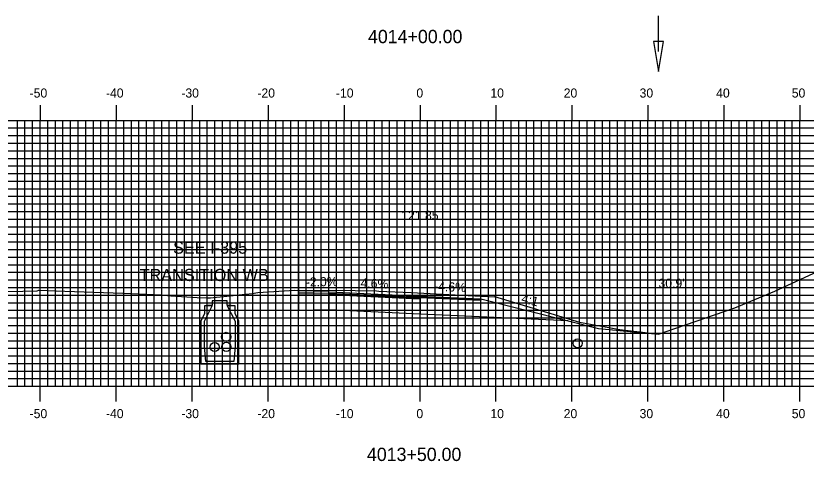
# Model space of a CAD drawing. Extents: x 853328 to 853671, y 364661 to 364881.
# Drawn here: x 853440.1 to 853544.1, y 364731.5 to 364790.1 of the extents above; entities that cross this region are included whole.
import ezdxf

# ---------------------------------------------------------------- set-up
doc = ezdxf.new("R2010")
doc.units = 0
for name, color, linetype in [('ANNOTATION', 7, 'Continuous'), ('D_Drainage_Ditch_Line', 7, 'Continuous'), ('D_Roadway_Centerline_Text', 7, 'Continuous'), ('D_Roadway_Edge_Shoulder', 7, 'Continuous'), ('D_Roadway_Edge_TW', 7, 'Continuous'), ('D_Roadway_Pavement', 7, 'Continuous'), ('D_Roadway_SubGrade', 7, 'Continuous'), ('D_Text_Standard', 7, 'Continuous'), ('H_V ANNOTATION', 7, 'Continuous'), ('M_Roadway_Centerline', 7, 'Continuous'), ('MAJOR', 7, 'Continuous'), ('MINOR', 7, 'Continuous'), ('S_Drainage_CB', 7, 'Continuous'), ('S_Drainage_Invert', 7, 'Continuous'), ('S_Roadway_Centerline', 7, 'Continuous')]:
    doc.layers.add(name, color=color, linetype=linetype)

msp = doc.modelspace()

# ---------------------------------------------------------------- linework, layer by layer
at = {"layer": 'ANNOTATION'}
for p, q in [((853512.79, 364749.99), (853516.79, 364748.99)), ((853516.79, 364748.99), (853524.69, 364748.23))]:
    msp.add_line(p, q, dxfattribs=at)
at = {"layer": 'D_Drainage_Ditch_Line'}
msp.add_line((853524.69, 364785.43), (853524.69, 364790.13), dxfattribs=at)
msp.add_lwpolyline([(853525.34, 364786.75), (853524.03, 364786.75), (853524.69, 364782.81)], close=True, dxfattribs=at)
at = {"layer": 'D_Roadway_Edge_Shoulder'}
for points in [[(853481.29, 364753.78), (853477.29, 364753.7), (853477.29, 364753.54), (853481.29, 364753.6)], [(853493.29, 364753.23), (853501.29, 364752.86), (853501.29, 364752.7), (853493.29, 364753.05)]]:
    msp.add_lwpolyline(points, close=True, dxfattribs=at)
at = {"layer": 'D_Roadway_Edge_TW'}
msp.add_lwpolyline([(853481.29, 364753.78), (853493.29, 364753.23), (853493.29, 364753.05), (853481.29, 364753.6)], close=True, dxfattribs=at)
at = {"layer": 'D_Roadway_Pavement'}
msp.add_lwpolyline([(853481.29, 364753.6), (853493.29, 364753.05), (853493.29, 364752.88), (853481.29, 364753.44)], close=True, dxfattribs=at)
for points in [[(853481.29, 364753.6), (853481.29, 364753.44)], [(853493.29, 364753.05), (853493.29, 364752.88)], [(853493.29, 364753.05), (853493.29, 364752.88)]]:
    msp.add_lwpolyline(points, dxfattribs=at)
at = {"layer": 'D_Roadway_SubGrade'}
msp.add_line((853477.29, 364760.39), (853477.29, 364751.36), dxfattribs=at)
for points in [[(853481.29, 364751.44), (853477.29, 364751.36), (853477.29, 364753.7), (853477.29, 364753.54), (853481.29, 364753.6), (853481.29, 364753.44)], [(853481.29, 364753.44), (853493.29, 364752.88), (853493.29, 364750.88), (853481.29, 364751.44)], [(853493.29, 364752.88), (853493.29, 364753.05), (853501.29, 364752.7), (853501.29, 364752.86), (853512.79, 364749.99), (853493.29, 364750.88)]]:
    msp.add_lwpolyline(points, close=True, dxfattribs=at)
at = {"layer": 'MAJOR'}
for p, q in [((853443.29, 364778.38), (853443.29, 364776.37)), ((853453.29, 364778.38), (853453.29, 364776.37)), ((853463.29, 364778.38), (853463.29, 364776.37)), ((853473.29, 364778.38), (853473.29, 364776.37)), ((853483.29, 364778.38), (853483.29, 364776.37)), ((853493.29, 364778.38), (853493.29, 364776.37)), ((853503.29, 364778.38), (853503.29, 364776.37)), ((853513.29, 364778.38), (853513.29, 364776.37)), ((853523.29, 364778.38), (853523.29, 364776.37)), ((853533.29, 364778.38), (853533.29, 364776.37)), ((853543.29, 364778.38), (853543.29, 364776.37)), ((853353.29, 364776.37), (853633.29, 364776.37)), ((853353.29, 364776.37), (853633.29, 364776.37)), ((853443.29, 364741.37), (853443.29, 364776.37)), ((853453.29, 364741.37), (853453.29, 364776.37)), ((853463.29, 364741.37), (853463.29, 364776.37)), ((853473.29, 364741.37), (853473.29, 364776.37)), ((853483.29, 364741.37), (853483.29, 364776.37)), ((853493.29, 364741.37), (853493.29, 364776.37)), ((853503.29, 364741.37), (853503.29, 364776.37)), ((853513.29, 364741.37), (853513.29, 364776.37)), ((853523.29, 364741.37), (853523.29, 364776.37)), ((853533.29, 364741.37), (853533.29, 364776.37)), ((853543.29, 364741.37), (853543.29, 364776.37)), ((853353.29, 364771.37), (853633.29, 364771.37)), ((853353.29, 364766.37), (853633.29, 364766.37)), ((853353.29, 364761.37), (853633.29, 364761.37)), ((853353.29, 364756.37), (853633.29, 364756.37)), ((853353.29, 364751.37), (853633.29, 364751.37)), ((853353.29, 364746.37), (853633.29, 364746.37)), ((853353.29, 364741.37), (853633.29, 364741.37)), ((853353.29, 364741.37), (853633.29, 364741.37)), ((853443.29, 364739.37), (853443.29, 364741.37)), ((853453.29, 364739.37), (853453.29, 364741.37)), ((853463.29, 364739.37), (853463.29, 364741.37)), ((853473.29, 364739.37), (853473.29, 364741.37)), ((853483.29, 364739.37), (853483.29, 364741.37)), ((853493.29, 364739.37), (853493.29, 364741.37)), ((853503.29, 364739.37), (853503.29, 364741.37)), ((853513.29, 364739.37), (853513.29, 364741.37)), ((853523.29, 364739.37), (853523.29, 364741.37)), ((853533.29, 364739.37), (853533.29, 364741.37)), ((853543.29, 364739.37), (853543.29, 364741.37))]:
    msp.add_line(p, q, dxfattribs=at)
at = {"layer": 'MINOR'}
for p, q in [((853440.29, 364741.37), (853440.29, 364776.37)), ((853441.29, 364741.37), (853441.29, 364776.37)), ((853442.29, 364741.37), (853442.29, 364776.37)), ((853444.29, 364741.37), (853444.29, 364776.37)), ((853445.29, 364741.37), (853445.29, 364776.37)), ((853446.29, 364741.37), (853446.29, 364776.37)), ((853447.29, 364741.37), (853447.29, 364776.37)), ((853448.29, 364741.37), (853448.29, 364776.37)), ((853449.29, 364741.37), (853449.29, 364776.37)), ((853450.29, 364741.37), (853450.29, 364776.37)), ((853451.29, 364741.37), (853451.29, 364776.37)), ((853452.29, 364741.37), (853452.29, 364776.37)), ((853454.29, 364741.37), (853454.29, 364776.37)), ((853455.29, 364741.37), (853455.29, 364776.37)), ((853456.29, 364741.37), (853456.29, 364776.37)), ((853457.29, 364741.37), (853457.29, 364776.37)), ((853458.29, 364741.37), (853458.29, 364776.37)), ((853459.29, 364741.37), (853459.29, 364776.37)), ((853460.29, 364741.37), (853460.29, 364776.37)), ((853461.29, 364741.37), (853461.29, 364776.37)), ((853462.29, 364741.37), (853462.29, 364776.37)), ((853464.29, 364741.37), (853464.29, 364776.37)), ((853465.29, 364741.37), (853465.29, 364776.37)), ((853466.29, 364741.37), (853466.29, 364776.37)), ((853467.29, 364741.37), (853467.29, 364776.37)), ((853468.29, 364741.37), (853468.29, 364776.37)), ((853469.29, 364741.37), (853469.29, 364776.37)), ((853470.29, 364741.37), (853470.29, 364776.37)), ((853471.29, 364741.37), (853471.29, 364776.37)), ((853472.29, 364741.37), (853472.29, 364776.37)), ((853474.29, 364741.37), (853474.29, 364776.37)), ((853475.29, 364741.37), (853475.29, 364776.37)), ((853476.29, 364741.37), (853476.29, 364776.37)), ((853477.29, 364741.37), (853477.29, 364776.37)), ((853478.29, 364741.37), (853478.29, 364776.37)), ((853479.29, 364741.37), (853479.29, 364776.37)), ((853480.29, 364741.37), (853480.29, 364776.37)), ((853481.29, 364741.37), (853481.29, 364776.37)), ((853482.29, 364741.37), (853482.29, 364776.37)), ((853484.29, 364741.37), (853484.29, 364776.37)), ((853485.29, 364741.37), (853485.29, 364776.37)), ((853486.29, 364741.37), (853486.29, 364776.37)), ((853487.29, 364741.37), (853487.29, 364776.37)), ((853488.29, 364741.37), (853488.29, 364776.37)), ((853489.29, 364741.37), (853489.29, 364776.37)), ((853490.29, 364741.37), (853490.29, 364776.37)), ((853491.29, 364741.37), (853491.29, 364776.37)), ((853492.29, 364741.37), (853492.29, 364776.37)), ((853494.29, 364741.37), (853494.29, 364776.37)), ((853495.29, 364741.37), (853495.29, 364776.37)), ((853496.29, 364741.37), (853496.29, 364776.37)), ((853497.29, 364741.37), (853497.29, 364776.37)), ((853498.29, 364741.37), (853498.29, 364776.37)), ((853499.29, 364741.37), (853499.29, 364776.37)), ((853500.29, 364741.37), (853500.29, 364776.37)), ((853501.29, 364741.37), (853501.29, 364776.37)), ((853502.29, 364741.37), (853502.29, 364776.37)), ((853504.29, 364741.37), (853504.29, 364776.37)), ((853505.29, 364741.37), (853505.29, 364776.37)), ((853506.29, 364741.37), (853506.29, 364776.37)), ((853507.29, 364741.37), (853507.29, 364776.37)), ((853508.29, 364741.37), (853508.29, 364776.37)), ((853509.29, 364741.37), (853509.29, 364776.37)), ((853510.29, 364741.37), (853510.29, 364776.37)), ((853511.29, 364741.37), (853511.29, 364776.37)), ((853512.29, 364741.37), (853512.29, 364776.37)), ((853514.29, 364741.37), (853514.29, 364776.37)), ((853515.29, 364741.37), (853515.29, 364776.37)), ((853516.29, 364741.37), (853516.29, 364776.37)), ((853517.29, 364741.37), (853517.29, 364776.37)), ((853518.29, 364741.37), (853518.29, 364776.37)), ((853519.29, 364741.37), (853519.29, 364776.37)), ((853520.29, 364741.37), (853520.29, 364776.37)), ((853521.29, 364741.37), (853521.29, 364776.37)), ((853522.29, 364741.37), (853522.29, 364776.37)), ((853524.29, 364741.37), (853524.29, 364776.37)), ((853525.29, 364741.37), (853525.29, 364776.37)), ((853526.29, 364741.37), (853526.29, 364776.37)), ((853527.29, 364741.37), (853527.29, 364776.37)), ((853528.29, 364741.37), (853528.29, 364776.37)), ((853529.29, 364741.37), (853529.29, 364776.37)), ((853530.29, 364741.37), (853530.29, 364776.37)), ((853531.29, 364741.37), (853531.29, 364776.37)), ((853532.29, 364741.37), (853532.29, 364776.37)), ((853534.29, 364741.37), (853534.29, 364776.37)), ((853535.29, 364741.37), (853535.29, 364776.37)), ((853536.29, 364741.37), (853536.29, 364776.37)), ((853537.29, 364741.37), (853537.29, 364776.37)), ((853538.29, 364741.37), (853538.29, 364776.37)), ((853539.29, 364741.37), (853539.29, 364776.37)), ((853540.29, 364741.37), (853540.29, 364776.37)), ((853541.29, 364741.37), (853541.29, 364776.37)), ((853542.29, 364741.37), (853542.29, 364776.37)), ((853353.29, 364775.37), (853633.29, 364775.37)), ((853353.29, 364774.37), (853633.29, 364774.37)), ((853353.29, 364773.37), (853633.29, 364773.37)), ((853353.29, 364772.37), (853633.29, 364772.37)), ((853353.29, 364770.37), (853633.29, 364770.37)), ((853353.29, 364769.37), (853633.29, 364769.37)), ((853353.29, 364768.37), (853633.29, 364768.37)), ((853353.29, 364767.37), (853633.29, 364767.37)), ((853353.29, 364765.37), (853633.29, 364765.37)), ((853353.29, 364764.37), (853633.29, 364764.37)), ((853353.29, 364763.37), (853633.29, 364763.37)), ((853353.29, 364762.37), (853633.29, 364762.37)), ((853353.29, 364760.37), (853633.29, 364760.37)), ((853353.29, 364759.37), (853633.29, 364759.37)), ((853353.29, 364758.37), (853633.29, 364758.37)), ((853353.29, 364757.37), (853633.29, 364757.37)), ((853353.29, 364755.37), (853633.29, 364755.37)), ((853353.29, 364754.37), (853633.29, 364754.37)), ((853353.29, 364753.37), (853633.29, 364753.37)), ((853353.29, 364752.37), (853633.29, 364752.37)), ((853353.29, 364750.37), (853633.29, 364750.37)), ((853353.29, 364749.37), (853633.29, 364749.37)), ((853353.29, 364748.37), (853633.29, 364748.37)), ((853353.29, 364747.37), (853633.29, 364747.37)), ((853353.29, 364745.37), (853633.29, 364745.37)), ((853353.29, 364744.37), (853633.29, 364744.37)), ((853353.29, 364743.37), (853633.29, 364743.37)), ((853353.29, 364742.37), (853633.29, 364742.37))]:
    msp.add_line(p, q, dxfattribs=at)
at = {"layer": 'S_Drainage_CB'}
for p, q in [((853465.92, 364751.94), (853464.93, 364751.94)), ((853464.93, 364751.94), (853464.93, 364750.96)), ((853464.93, 364749.94), (853465.92, 364751.94)), ((853468.94, 364751.94), (853467.92, 364751.94)), ((853467.92, 364751.94), (853468.94, 364749.94)), ((853468.94, 364750.96), (853468.94, 364751.94)), ((853464.93, 364750.96), (853464.44, 364749.94)), ((853469.43, 364749.94), (853468.94, 364750.96)), ((853464.44, 364749.94), (853464.44, 364744.3)), ((853464.93, 364746.63), (853464.93, 364749.94)), ((853468.94, 364749.94), (853468.94, 364746.63)), ((853469.43, 364744.3), (853469.43, 364749.94)), ((853465.1, 364744.62), (853464.93, 364746.63)), ((853468.94, 364746.63), (853468.77, 364744.62)), ((853464.44, 364744.3), (853469.43, 364744.3)), ((853468.77, 364744.62), (853465.1, 364744.62))]:
    msp.add_line(p, q, dxfattribs=at)
msp.add_lwpolyline([(853468.41, 364751.98), (853467.92, 364751.98), (853467.92, 364752.61), (853465.92, 364752.61), (853465.92, 364751.98), (853465.42, 364751.98)], dxfattribs=at)
at = {"layer": 'S_Drainage_Invert'}
for centre in [(853467.77, 364747.87), (853514.05, 364747.03), (853466.26, 364746.53), (853467.8, 364746.56)]:
    msp.add_circle(centre, 0.6, dxfattribs=at)
at = {"layer": 'S_Roadway_Centerline'}
msp.add_lwpolyline([(853433.91, 364753.78), (853441.02, 364753.88), (853442.88, 364753.92), (853443.12, 364754), (853446.52, 364753.87), (853454.19, 364753.64), (853459.21, 364753.41), (853460.5, 364753.27), (853461.14, 364753.23), (853461.88, 364753.2), (853463.96, 364753.07), (853465.33, 364752.99), (853465.71, 364753.02), (853466.1, 364753.07), (853466.48, 364753.1), (853467.47, 364753.2), (853469.11, 364753.35), (853470.28, 364753.47), (853470.38, 364753.49), (853471.18, 364753.6), (853471.96, 364753.71), (853471.96, 364753.71), (853471.96, 364753.71), (853476.8, 364754), (853484.74, 364753.98), (853487.57, 364753.92), (853487.86, 364753.9), (853492.11, 364753.69), (853497.91, 364753.39), (853503.05, 364753.15), (853503.1, 364753.18), (853514.27, 364749.81), (853519.58, 364748.82), (853523.68, 364748.34), (853524.69, 364748.23), (853528.25, 364749.46), (853534.73, 364751.71), (853539.98, 364753.87), (853559.29, 364762.8)], dxfattribs=at)

# ---------------------------------------------------------------- texts
at = {"layer": 'ANNOTATION'}
for s, p in [('SEE I-395 ', (853460.79, 364758.82)), ('TRANSITION WB', (853456.38, 364755.22))]:
    msp.add_text(s, height=1.6, dxfattribs=at).set_placement(p)
for s, rotation, p in [('-2.0%', 1.1458, (853478.26, 364754.49)), ('4.6%', 357.3663, (853485.44, 364754.39)), ('-4.6%', 357.3663, (853495.12, 364753.95)), ('4:1', 345.9638, (853506.55, 364752.41))]:
    msp.add_text(s, height=1.2, rotation=rotation, dxfattribs=at).set_placement(p)
at = {"layer": 'D_Roadway_Centerline_Text'}
msp.add_text('121.85', height=1.2, dxfattribs=at).set_placement((853490.82, 364763.26))
at = {"layer": 'D_Text_Standard'}
msp.add_text("30.9'", height=1.2, dxfattribs=at).set_placement((853524.68, 364754.33))
at = {"layer": 'H_V ANNOTATION'}
for s, height, p in [('4014+00.00', 1.75, (853486.44, 364786.53)), ('-50', 1.2, (853441.9, 364779.37)), ('-40', 1.2, (853451.95, 364779.37)), ('-30', 1.2, (853461.87, 364779.37)), ('-20', 1.2, (853471.88, 364779.37)), ('-10', 1.2, (853482.22, 364779.37)), ('0', 1.2, (853492.81, 364779.37)), ('10', 1.2, (853502.55, 364779.37)), ('20', 1.2, (853512.2, 364779.37)), ('30', 1.2, (853522.19, 364779.37)), ('40', 1.2, (853532.27, 364779.37)), ('50', 1.2, (853542.22, 364779.37)), ('-50', 1.2, (853441.9, 364737.17)), ('-40', 1.2, (853451.95, 364737.17)), ('-30', 1.2, (853461.87, 364737.17)), ('-20', 1.2, (853471.88, 364737.17)), ('-10', 1.2, (853482.22, 364737.17)), ('0', 1.2, (853492.81, 364737.17)), ('10', 1.2, (853502.55, 364737.17)), ('20', 1.2, (853512.2, 364737.17)), ('30', 1.2, (853522.19, 364737.17)), ('40', 1.2, (853532.27, 364737.17)), ('50', 1.2, (853542.22, 364737.17)), ('4013+50.00', 1.75, (853486.3, 364731.53))]:
    msp.add_text(s, height=height, dxfattribs=at).set_placement(p)
at = {"layer": 'M_Roadway_Centerline'}
for s, p in [('C', (853443.11, 364754)), ('L', (853443.12, 364753.99)), ('C', (853487.56, 364753.92)), ('L', (853487.57, 364753.91))]:
    msp.add_text(s, height=0.0146, dxfattribs=at).set_placement(p)

doc.saveas('drawing.dxf')
